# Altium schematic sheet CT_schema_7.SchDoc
size 299 x 230 mm
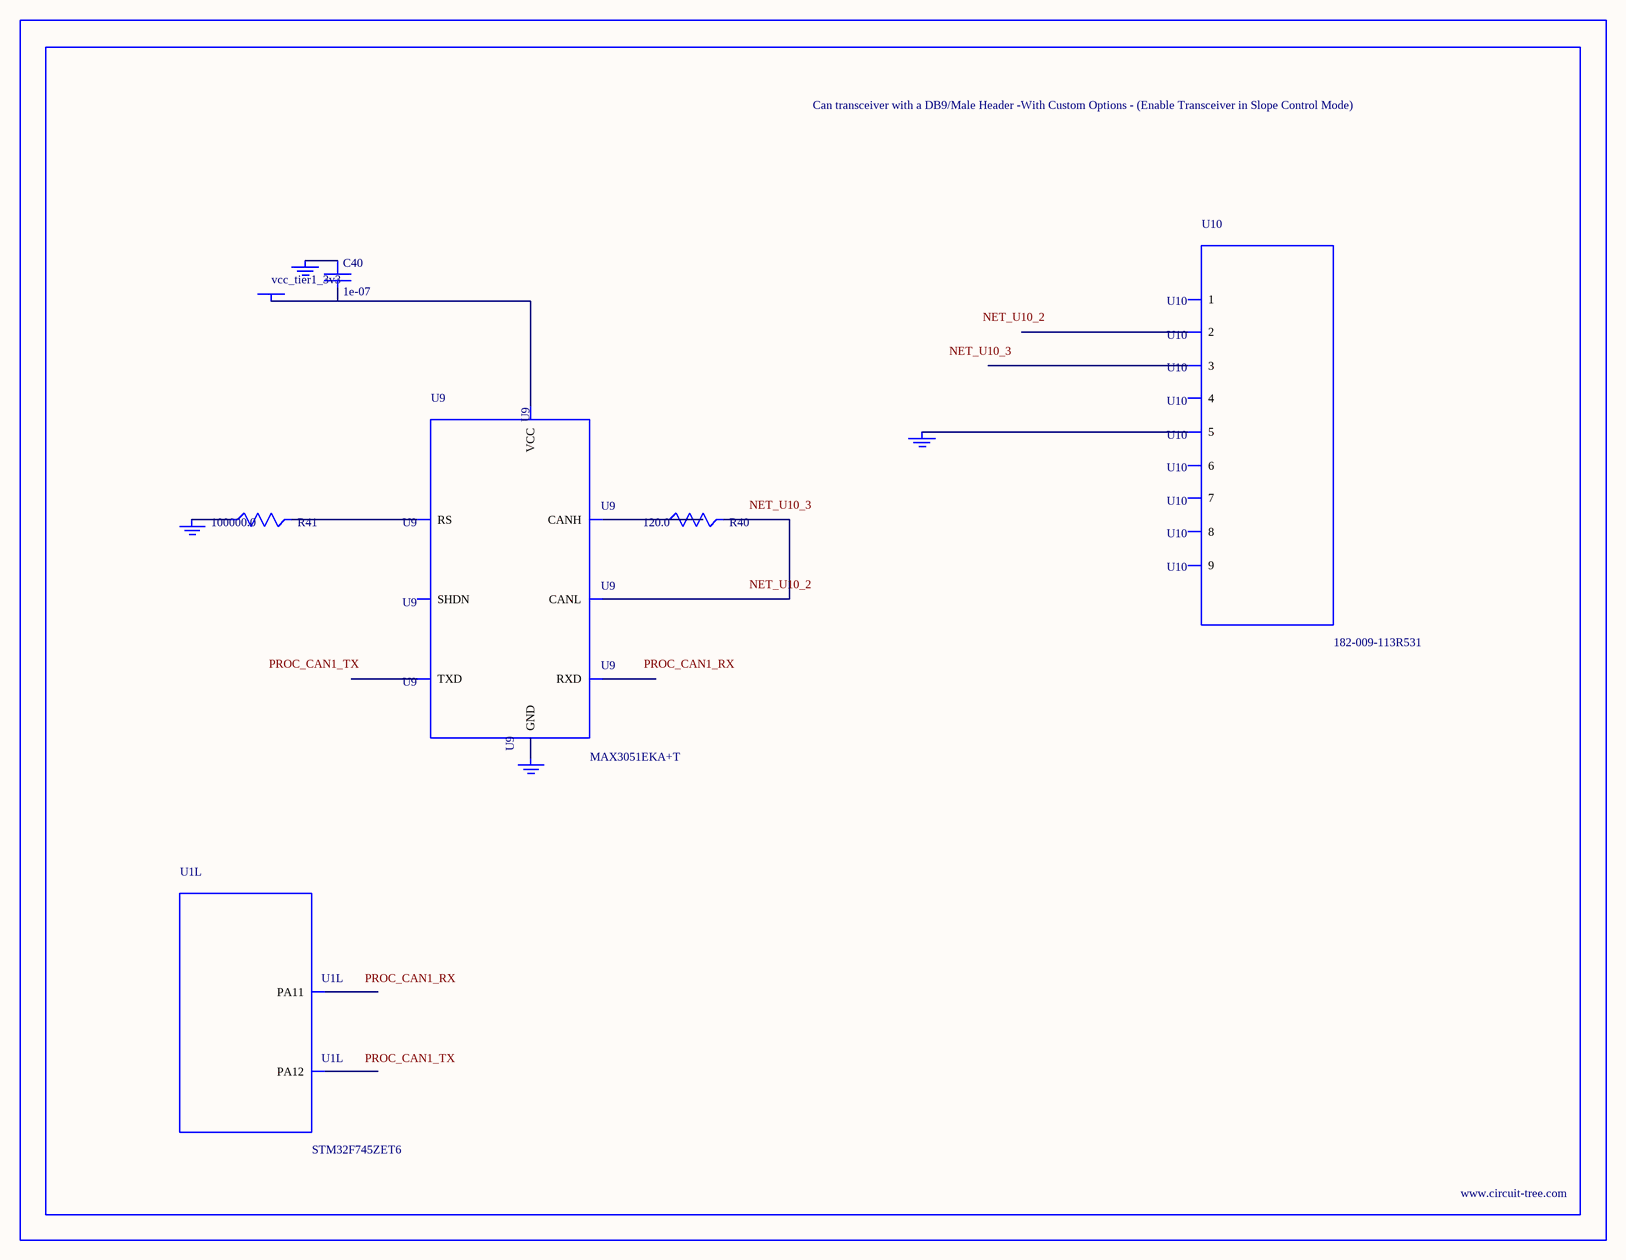
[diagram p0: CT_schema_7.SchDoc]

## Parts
BORDER6  (no value)
C40  1e-07  [C0402]
GND_INSTANCE_6_0  (no value)
GND_INSTANCE_6_1  (no value)
GND_INSTANCE_6_2  (no value)
GND_INSTANCE_6_3  (no value)
POWER_INSTANCE_6_0  vcc_tier1_3v3
R40  120.0  [R0603]
R41  100000.0  [R0603]
U1  STM32F745ZET6  [LQFP144]  (part L of 12)
U9  MAX3051EKA+T  [SOT-23-8]
U10  182-009-113R531  [182-009-MALE]

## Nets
NetC40_1: C40.1 GND_INSTANCE_6_0.0(GND)
NetC40_2: C40.2 POWER_INSTANCE_6_0.0(PWR) U9.3(VCC)
NetGND_INSTANCE_6_1_0: GND_INSTANCE_6_1.0(GND) R41.1
NetGND_INSTANCE_6_2_0: GND_INSTANCE_6_2.0(GND) U9.2(GND)
NetGND_INSTANCE_6_3_0: GND_INSTANCE_6_3.0(GND) U10.5
NetR40_1: R40.1 U9.7(CANH)
NetR40_2: R40.2 U9.6(CANL)
NetR41_2: R41.2 U9.8(RS)

Not connected (* = marked no-connect by the designer): U1 103(PA11) 104(PA12); U9 1(TXD) 4(RXD) 5(SHDN); U10 1 2 3 4 6 7 8 9

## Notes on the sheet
- Labels drawn without touching a wire or pin: NET_U10_2, NET_U10_3, PROC_CAN1_RX, PROC_CAN1_TX

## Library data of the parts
BORDER6 = BORDER_PAGE6
C40 = C0402C104K3RACTU
GND_INSTANCE_6_0-GND_INSTANCE_6_3 = GND
POWER_INSTANCE_6_0 = PWR
R40 = RC0603JR-07120RL
R41 = RC0603JR-07100KL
